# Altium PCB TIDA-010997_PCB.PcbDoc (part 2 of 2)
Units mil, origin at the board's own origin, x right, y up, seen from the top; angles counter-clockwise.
Board outline 2300 x 1800 mil, 2 copper layers (Top Layer, Bottom Layer), stack 62 mil thick; 121 components, 80 nets, 346 pads, 277 vias.
Unrouted connection lines stored in the file: 141.
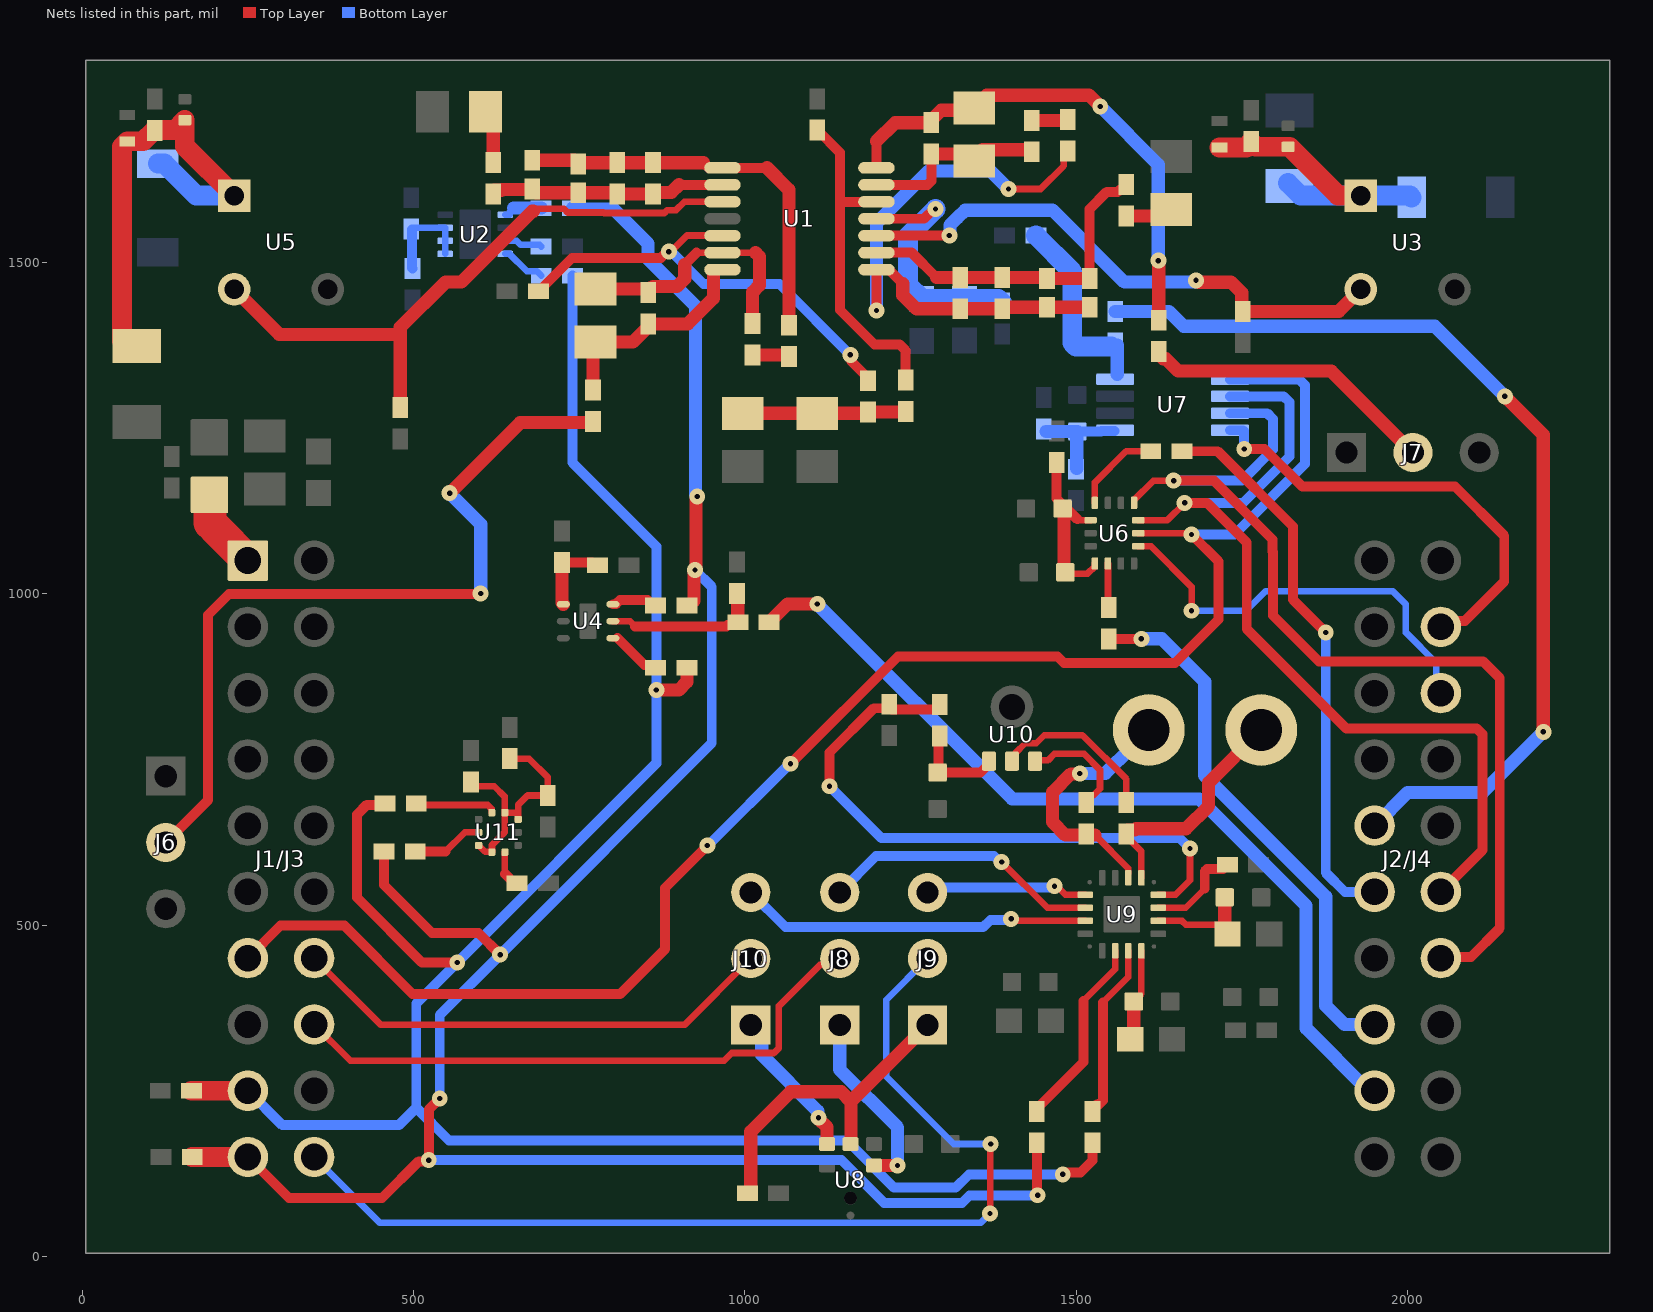
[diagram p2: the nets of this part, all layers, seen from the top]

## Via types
v1: diameter 24, hole 8, Top Layer to Bottom Layer, tented both sides, 271 vias
v2: diameter 19.68, hole 7.87, Top Layer to Bottom Layer, tented both sides, 6 vias

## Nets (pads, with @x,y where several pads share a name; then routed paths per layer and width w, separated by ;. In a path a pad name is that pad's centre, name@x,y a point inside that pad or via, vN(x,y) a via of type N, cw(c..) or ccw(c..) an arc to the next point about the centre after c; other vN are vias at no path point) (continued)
I2C_SCL: J1/J3.9 R6.1 R17.1 R21.2 R39.2 R44.1 | length 3379.6
  Top Layer w15: R44.1@456.84,683.31 454.94,681.41 429.35,681.41 414.46,666.52 414.46,541.58 512.41,443.63 v1(565.9,443.63) ; v1(1479.54,123.81) 1482.21,126.49 1506.15,126.49 1524.32,144.66 R39.2@1524.32,171.5
  Top Layer w20: v1(866.29,854.65) 900.16,854.65 912.5,866.99 R21.2@912.5,887.99
  Top Layer w30: R17.1@165.08,250 J1/J3.9@249.96,250
  Bottom Layer w15: J1/J3.9@249.96,250 301.96,198 477.77,198 504.08,224.31 ; v1(565.9,443.63) 504.08,381.81 504.08,224.31 ; v1@567.62,445.35 866.29,744.02 v1(866.29,854.65) 866.29,1071.22 739.84,1197.67 R6.1@739.84,1479.94 ; v1(1479.54,123.81) 1337.94,123.81 1317.85,103.72 1225.12,103.72 1153.97,174.87 553.52,174.87 504.08,224.31
I2C_SDA: J1/J3.10 R8.1 R18.1 R22.2 R38.2 R45.1 | length 3505.2
  Top Layer w10: R22.2@912.5,982.24 916.43,982.24 R22.2@923.24,989.05 ; v1@923.24,1035.69 v1@926.32,1038.77 ; v1@926.32,1144.8 v1(928.02,1146.5) ; R38.2@1440.09,171.5 R38.2@1440.88,170.72 ; v1@1440.88,93.12 v1(1441.66,92.34)
  Top Layer w15: J1/J3.10@249.96,150 312,87.96 452.27,87.96 507.85,143.54 521.24,143.54 v1(522.96,145.26) 522.96,221.63 v1(539.52,238.19) ; R45.1@455.34,611.07 455.34,560.6 527.9,488.03 597.94,488.03 v1(630.69,455.28) ; v1@1440.88,93.12 R38.2@1440.88,170.72
  Top Layer w20: R22.2@923.24,989.05 v1@923.24,1035.69 ; v1@926.32,1038.77 v1@926.32,1144.8
  Top Layer w30: R18.1@166.08,150 J1/J3.10@249.96,150
  Bottom Layer w15: v1(522.96,145.26) 1145.72,145.26 1210.13,80.85 1327.33,80.85 1338.62,92.14 1441.47,92.14 v1(1441.66,92.34) ; v1(539.52,238.19) 539.52,364.12 v1(630.69,455.28) 949.93,774.52 949.93,1010.38 v1(924.62,1035.69)
  Bottom Layer w20: R8.1@739.78,1581.82 741.5,1580.11 802,1580.11 853.59,1528.52 853.59,1505.42 925.43,1433.57 925.43,1149.09 v1(928.02,1146.5)
I2S_SCLK: J1/J3.28 J8.2 | length 916.8
  Top Layer w10: J1/J3.28@349.96,350 404.68,295.28 968.46,295.28 980.12,306.93 1043.7,306.93 1051.25,314.47 1051.25,378.06 1113.13,439.94 1133.6,439.94 J8.2@1142.99,449.33
I2S_SCLK_DMIC: J8.1 U8.4 | length 283.9
  Top Layer w20: U8.4@1194.69,137.25 v1(1230.32,137.25)
  Bottom Layer w20: J8.1@1142.99,349.33 1142.99,282.01 1230.32,194.68 v1(1230.32,137.25)
I2S_SCLK_TAA: J8.3 U9.7 | length 425.6
  Top Layer w10: v1(1387.26,595.05) 1456.29,526.02 U9.7@1513.5,526.02
  Bottom Layer w15: J8.3@1142.99,549.33 1197.79,604.13 1375.74,604.13 1384.82,595.05 v1(1387.26,595.05)
I2S_SD: J1/J3.30 J9.2 | length 1575.4
  Top Layer w10: v1(1369.75,64.76) 1370.27,65.29 1370.27,169.09 v1(1370.8,169.61)
  Bottom Layer w10: J1/J3.30@349.96,150 449.31,50.65 1355.63,50.65 v1(1369.75,64.76) ; J9.2@1275.52,449.33 1213.24,387.05 1213.24,271.54 1315.17,169.61 v1(1370.8,169.61)
I2S_SD_DMIC: J9.1 R36.2 U8.6 | length 504.9
  Top Layer w20: R36.2@1003.61,95.41 1008.84,100.64 1008.84,188.47 1068.85,248.48 1145.25,248.48 1159.96,233.77 ; U8.6@1159.96,169.61 1159.96,233.77 ; J9.1@1275.52,349.33 1159.96,233.77
I2S_SD_TAA: J9.3 U9.6 | length 247.9
  Top Layer w10: v1(1466.95,558.65) 1470.74,558.65 1483.68,545.71 U9.6@1513.5,545.71
  Bottom Layer w15: J9.3@1275.52,549.33 1283.95,557.76 1284.79,556.93 1465.23,556.93 v1(1466.95,558.65)
I2S_WS: J1/J3.27 J10.2 | length 742
  Top Layer w10: J1/J3.27@349.96,450 450.63,349.33 908.84,349.33 J10.2@1008.84,449.33
I2S_WS_DMIC: J10.1 U8.1 | length 227.3
  Top Layer w20: v1(1110.85,209.26) 1110.85,207.87 1123.83,194.89 U8.1@1123.83,169.61
  Bottom Layer w20: J10.1@1008.84,349.33 1025.23,332.94 1025.23,304.23 1110.08,219.38 1110.08,210.02 v1(1110.85,209.26)
I2S_WS_TAA: J10.3 U9.8 | length 532.8
  Top Layer w10: v1(1401.6,509.33) 1404.27,506.65 1414.14,506.65 1414.45,506.34 U9.8@1513.5,506.34
  Bottom Layer w15: J10.3@1008.84,549.33 1061.34,496.84 1359.6,496.84 1370.37,507.61 1399.87,507.61 v1(1401.6,509.33)
INERT_INTR1: J2/J4.35 R32.1 | length 842.9
  Top Layer w15: R32.1@1659.57,1214.91 1713.38,1214.91 1826.85,1101.44 1826.85,990.9 v1(1876.32,941.43)
  Bottom Layer w15: v1(1876.32,941.43) 1876.32,578.92 1905.24,550 J2/J4.35@1950,550
INERT_INTR2: J2/J4.33 R33.1 | length 821.2
  Top Layer w15: R33.1@1549.14,931.89 v1(1598.14,931.89)
  Bottom Layer w20: v1(1598.14,931.89) 1628.9,931.89 1693.81,866.99 1693.81,725.55 1876.32,543.04 1876.32,378.27 1904.49,350.11 1949.89,350.11 J2/J4.33@1950,350
Magnet_INTR: J2/J4.36 R35.1 | length 1484.7
  Top Layer w20: v1(2146.57,1297.82) 2204.72,1239.66 v1(2204.72,791.55)
  Bottom Layer w20: R35.1@1558.57,1425.82 1639.78,1425.82 1662.08,1403.52 2040.86,1403.52 v1(2146.57,1297.82) ; J2/J4.36@1950,650 2000.04,700.04 2113.21,700.04 v1(2204.72,791.55)
NetC4_1: C4.1 C5.1 R3.2 U1.4 | length 380.9
  Top Layer w15: U1.4@1198.38,1565.73 1270.21,1565.73 1285.07,1580.58 v1(1287.51,1580.58)
  Bottom Layer w30: v1(1287.51,1580.58) 1246.18,1539.25 1246.18,1465.98 1266.73,1445.42 C4.1@1266.73,1444.44 1330.77,1444.44 C5.1@1331.11,1444.78 1382.13,1444.78 R3.2@1387.99,1438.92
NetC6_1: C6.1 R2.1 U2.5 U2.6 U2.7 | length 149.9
  Bottom Layer w10: C6.1@497.46,1549.24 500.23,1552.01 U2.7@547.68,1552.01 U2.6@547.68,1532.32 U2.5@547.68,1512.64
  Bottom Layer w15: C6.1@497.46,1549.24 497.46,1491.51 R2.1@498.46,1490.51
NetC7_1: C7.1 C13.2 D1.2 D2.1 R11.2 U1.1 | length 917
  Top Layer w10: v1(1397.55,1610.69) 1446.15,1610.69 1481.02,1645.56 1481.02,1661.84 C13.2@1487.27,1668.08
  Top Layer w15: v1(1198.38,1427.33) U1.1@1198.38,1488.95 1217.08,1488.95 1238.26,1467.78
  Top Layer w20: 1238.26,1467.78 1238.26,1450.33 1258.7,1429.89 C7.1@1325,1429.89 1325.08,1429.97 R11.2@1387.99,1429.97 1390.24,1432.22 D1.2@1455.85,1432.22 D2.1@1520.16,1432.22
  Bottom Layer w20: v1(1198.38,1427.33) 1198.38,1559.22 1277.07,1637.91 1370.33,1637.91 v1(1397.55,1610.69)
NetC7_2: C7.2 D1.1 D2.2 R7.2 R11.1 U1.2 | length 515.8
  Top Layer w15: U1.2@1198.38,1514.55 1251.7,1514.55 1289.11,1477.13 ; D1.1@1454.17,1477.21 D1.1@1455.85,1475.53 ; D2.2@1520.16,1475.53 1520.16,1580.58 1545.97,1606.4 1562.43,1606.4 1564.93,1608.9 1571.22,1608.9 1575.53,1613.21 R7.2@1575.53,1617.15
  Top Layer w20: 1289.11,1477.13 C7.2@1325,1477.13 R11.1@1387.91,1477.13 ; R11.1@1387.99,1477.21 D1.1@1454.17,1477.21 ; D1.1@1455.85,1475.53 D2.2@1520.16,1475.53
NetC8_2: C8.2 C10.1 C11.1 C44.1 R5.1 U3.1 | length 447.8
  Top Layer w30: C11.1@1715.91,1673.35 1757,1673.35 1763.81,1680.16 C10.1@1763.81,1682.15 1763.81,1681.09 1770.63,1674.28 C8.2@1819.54,1674.28 1821.51,1674.28 1895.08,1600.71 U3.1@1929.29,1600.71
  Bottom Layer w30: R5.1@1819.54,1619.48 1838.31,1600.71 U3.1@1929.29,1600.71 2003.22,1600.71 C44.1@2005.91,1598.03
NetC9_1: C9.1 R9.2 R13.1 U1.7 | length 775
  Top Layer w10: R9.2@1345.87,1732.85 R9.2@1365.04,1752.01 ; v1(1623.73,1502.54) v1@1624.34,1501.94
  Top Layer w15: U1.7@1198.38,1642.5 1198.38,1682.5
  Top Layer w20: 1198.38,1682.5 1226.62,1710.75 C9.1@1281.19,1710.75 1281.19,1714.68 1296.09,1729.58 1342.61,1729.58 R9.2@1345.87,1732.85 ; R9.2@1365.04,1752.01 1519.28,1752.01 v1(1536.08,1735.21) ; R13.1@1624.34,1412.49 v1@1624.34,1501.94
  Bottom Layer w20: v1(1536.08,1735.21) 1623.73,1647.56 v1(1623.73,1502.54)
NetC9_2: C9.2 R9.1 R12.2 U1.6 | length 281.1
  Top Layer w10: R9.1@1352.2,1663.5 R9.1@1358.41,1669.71 ; R12.2@1429.66,1669.71 R12.2@1432.53,1666.84
  Top Layer w15: U1.6@1198.38,1616.91 1275.33,1616.91 1281.19,1622.77 C9.2@1281.19,1663.5
  Top Layer w20: C9.2@1281.19,1663.5 R9.1@1352.2,1663.5 ; R9.1@1358.41,1669.71 R12.2@1429.66,1669.71
NetC12_1: C12.1 R7.1 | length 71.7
  Top Layer w10: C12.1@1633.53,1569.9 C12.1@1643.21,1579.59
  Top Layer w20: R7.1@1575.53,1569.9 C12.1@1633.53,1569.9
NetC13_1: C13.1 R12.1 | length 55.3
  Top Layer w10: C13.1@1486.02,1714.08 C13.1@1487.27,1715.33
  Top Layer w20: R12.1@1432.53,1714.08 C13.1@1486.02,1714.08
NetC14_1: C14.1 R16.1 U1.5 | length 509.6
  Top Layer w15: C14.1@1109.29,1699.43 1143.35,1665.37 1143.35,1591.32 ; U1.5@1198.38,1591.32 1143.35,1591.32 ; R16.1@1242.38,1322.33 1242.38,1367.34 1233.6,1376.13 1195.38,1376.13 1143.35,1428.15 1143.35,1591.32
NetC15_1: C15.1 R20.1 U4.1 | length 119.5
  Top Layer w15: R20.1@723.87,1047.12 769.37,1047.12 773.75,1042.74 C15.1@777.68,1042.74
  Top Layer w20: R20.1@723.87,1047.12 723.87,986.07 U4.1@725.85,984.08
NetC16_1: C16.1 C22.2 D3.2 D4.1 R27.2 U1.8 | length 612
  Top Layer w15: 937.48,1650.32 945.31,1642.5 U1.8@966.1,1642.5 1033.27,1642.5
  Top Layer w20: D3.2@678.92,1654 742.69,1654 D4.1@748.33,1648.35 750.3,1650.32 R27.2@807.58,1650.32 937.48,1650.32 ; 1033.27,1642.5 1066.37,1609.41 C22.2@1066.37,1404.97
NetC16_2: C16.2 D3.1 D4.2 R25.2 R27.1 U1.9 | length 360.3
  Top Layer w15: 900.5,1616.91 U1.9@966.1,1616.91
  Top Layer w20: R25.2@620.08,1603.08 620.08,1607.02 621.89,1608.83 632.54,1608.83 633.61,1609.89 D3.1@678.92,1609.89 ; D3.1@678.92,1610.69 684.56,1605.05 D4.2@748.33,1605.05 805.61,1605.05 R27.1@807.58,1603.08 C16.2@861.34,1603.08 861.34,1603.6 863.15,1605.41 889,1605.41 900.5,1616.91
NetC17_2: C17.2 C19.1 C20.1 C45.1 R24.1 U5.1 | length 695.7
  Top Layer w30: R24.1@67.95,1373.29 60,1381.24 60,1674.44 68.14,1682.59 91.89,1682.59 108.26,1698.97 C19.1@109.46,1698.97 110.21,1699.72 140.01,1699.72 C17.2@154.8,1714.51 154.8,1699.72 154.8,1675.2 U5.1@229.29,1600.71
  Bottom Layer w30: C45.1@114.09,1648.92 123.93,1648.92 172.14,1600.71 U5.1@229.29,1600.71
NetC18_1: C18.1 R26.2 R29.1 U1.14 | length 336.3
  Top Layer w15: U1.14@952.39,1485.39 955.96,1488.95 U1.14@966.1,1488.95
  Top Layer w20: R29.1@770.83,1307.3 770.83,1376.13 R26.2@774.33,1379.63 830.86,1379.63 854.3,1403.07 C18.1@854.3,1407.01 913.62,1407.01 952.39,1445.78 U1.14@952.39,1485.39
NetC18_2: C18.2 R26.1 R28.2 U1.13 | length 394.2
  Top Layer w10: 926.94,1514.55 1016.03,1514.55
  Top Layer w15: 909.25,1496.85 926.94,1514.55
  Top Layer w20: R26.1@774.33,1459.63 848.92,1459.63 C18.2@854.3,1454.25 ; C18.2@854.3,1456.81 861.11,1463.62 897.52,1463.62 909.25,1475.35 909.25,1496.85 ; R28.2@1011.48,1407.48 1011.48,1454.92 1021.89,1465.33 1021.89,1508.69 1016.03,1514.55
NetC21_1: C21.1 R25.1 | length 81.6
  Top Layer w10: C21.1@608.46,1727.12 C21.1@620.08,1715.51
  Top Layer w20: R25.1@620.08,1650.32 C21.1@620.08,1715.51
NetC22_1: C22.1 R28.1 | length 55.9
  Top Layer w10: C22.1@1063.86,1360.23 C22.1@1066.37,1357.73
  Top Layer w20: R28.1@1011.48,1360.23 C22.1@1063.86,1360.23
NetC23_1: C23.1 R31.1 U1.12 | length 699.2
  Top Layer w10: v1@888.18,1516.14 912.5,1540.45 U1.12@965.78,1540.45 ; R31.1@1185.62,1321.33 R31.1@1185.62,1325.27
  Top Layer w15: C23.1@689.29,1456.96 693.23,1456.96 696.71,1460.44 696.71,1464.38 738.85,1506.51 873.06,1506.51 882.68,1516.14 v1(885.12,1516.14) ; U1.12@965.78,1540.45 U1.12@966.1,1540.14 ; v1(1159.02,1360.37) 1160.74,1358.64 1160.74,1350.15 R31.1@1185.62,1325.27
  Bottom Layer w15: v1(885.12,1516.14) 888.73,1516.14 937.56,1467.3 1052.08,1467.3 v1(1159.02,1360.37)
NetC24_2: C24.2 C25.2 R40.1 U6.5 U6.8 | length 271.8
  Top Layer w10: C24.2@1479.34,1128.35 C24.2@1481.38,1126.32 ; C25.2@1481.38,1034.29 1485.42,1030.24 1517.02,1030.24 1528,1041.22 U6.8@1528,1045.49 ; 1501.53,1112.3 1502.89,1110.94 U6.5@1521.6,1110.94
  Top Layer w15: 1470.03,1143.29 1470.29,1143.55 ; R40.1@1470.29,1198.12 1470.29,1143.55 ; 1501.53,1112.3 1470.29,1143.55
  Top Layer w20: C25.2@1481.38,1034.29 C24.2@1481.38,1126.32
NetC26_2: C26.2 C27.1 R34.1 U7.5 | length 168.2
  Bottom Layer w10: C27.1@1450.66,1248.6 C27.1@1454.6,1244.67
  Bottom Layer w15: R34.1@1499.43,1187.7 R34.1@1500.52,1188.78 ; C26.2@1500.52,1243.58 C26.2@1502.58,1245.65 ; C26.2@1501.6,1244.67 1536.92,1244.67 1537.9,1245.65 U7.5@1557.59,1245.65
  Bottom Layer w20: C27.1@1454.6,1244.67 C26.2@1501.6,1244.67 ; R34.1@1500.52,1188.78 C26.2@1500.52,1243.58
NetC33_1: C33.1 C37.2 U9.17 | length 169.3
  Top Layer w10: U9.17@1623.73,506.34 1659.57,506.34 1665.55,500.35 1714.35,500.35 C37.2@1728.06,486.65 C37.2@1723.93,490.78
  Top Layer w20: C37.2@1723.93,490.78 C33.1@1723.93,541.77
NetC34_1: C34.1 C38.2 U9.14 | length 140.2
  Top Layer w10: C38.2@1581.41,327.78 C38.2@1586.56,332.94 ; C34.1@1586.56,384.57 1598.14,396.15 U9.14@1598.14,461.06
  Top Layer w20: C38.2@1586.56,332.94 C34.1@1586.56,384.57
NetC35_1: C35.1 R37.2 U9.19 | length 945.7
  Top Layer w10: U9.19@1623.73,545.71 1649.57,545.71 1671.47,567.61 v1(1671.47,615.44)
  Top Layer w15: v1(1127.58,709.43) 1127.58,760.28 1194.42,827.12 1213.44,827.12 1217.76,831.43 C35.1@1217.76,833.17 1217.76,829.82 1222.07,825.51 1289.58,825.51 1293.89,829.82 R37.2@1293.89,832.78
  Bottom Layer w15: v1(1127.58,709.43) 1205.65,631.37 1655.55,631.37 v1(1671.47,615.44)
NetC36_1: C36.1 U9.18 | length 146.5
  Top Layer w10: U9.18@1623.73,526.02 1665.02,526.02 1693.81,554.81 ; C36.1@1721.33,584.45 C36.1@1727.86,590.98
  Top Layer w15: 1693.81,554.81 1693.81,581.14 1697.12,584.45 C36.1@1721.33,584.45
NetC39_2: C39.2 R37.1 U10.1 | length 143.5
  Top Layer w15: R37.1@1293.89,785.54 1292.32,783.96 1292.32,731.81 C39.2@1290.74,730.23 1355.27,730.23 1368.28,743.25 U10.1@1368.28,747.18
NetC40_1: C40.1 U10.2 | length 255.9
  Top Layer w10: U10.2@1402.93,747.18 1408.36,752.62 1408.36,759.82 1422.97,774.43 1439.54,774.43 1451.58,786.46 1509.21,786.46 1575.53,720.14 C40.1@1575.53,684.79
NetC40_2: C40.2 TP1.1 U9.1 | length 363.2
  Top Layer w10: C40.2@1575.53,633.61 1598.14,610.99 U9.1@1598.14,571.3
  Top Layer w20: C40.2@1575.53,637.55 1575.53,641.48 1577.34,643.29 1588.42,643.29 1590.45,645.32 1665.34,645.32 1699.57,679.54 1699.57,714.9 TP1.1@1779.04,794.38
NetC41_1: C41.1 U10.3 | length 173.1
  Top Layer w10: U10.3@1437.57,747.18 1438.9,748.51 1457.15,748.51 1467.01,758.37 1511.54,758.37 1535.7,734.21 1535.7,705.72 1525.6,695.61 1521.66,695.61 1514.85,688.8 C41.1@1514.85,684.86
NetC41_2: C41.2 TP2.1 U9.2 | length 396.2
  Top Layer w10: 1528.12,635.74 1578.38,585.48 U9.2@1578.38,578.11
  Top Layer w20: v1(1505.3,728.78) 1504.54,728.01 1491.83,728.01 1464.08,700.26 1464.08,655.32 1483.62,635.78 1513.04,635.78 C41.2@1514.85,637.62 ; C41.2@1514.85,635.74 1528.12,635.74
  Bottom Layer w20: v1(1505.3,728.78) 1543.78,728.78 1582.79,767.79 1582.79,794.38 TP2.1@1609.38,794.38
NetC42_1: C42.1 C43.1 R42.1 U11.1 U11.5 U11.6 U11.10 | length 366.1
  Top Layer w10: C42.1@586.54,715.95 593.05,709.43 621.86,709.43 637.41,693.89 637.41,639.84 618.35,620.78 618.35,610.33 U11.6@618.04,610.02 618.04,610.31 617.72,610.63 607.88,610.63 598.35,620.15 U11.5@598.06,620.15 ; U11.1@637.72,669.66 657.06,669.66 657.8,670.4 ; R42.1@645.05,751.03 674.32,751.03 702.68,722.67 C43.1@702.68,695.48 672.1,695.48 657.8,681.18 657.8,670.4 ; U11.10@657.39,659.84 U11.10@657.7,659.52 657.8,659.62 657.8,670.4
NetJ1/J3_1: J1/J3.1 R1.2 | length 123.1
  Top Layer w20: R1.2@192,1149.07 R1.2@201.16,1139.91
  Top Layer w50: 192.99,1106.97 R1.2@192.99,1148.08 ; 201.16,1098.8 J1/J3.1@249.96,1050
NetR4_1: R4.1 U2.3 | length 57.8
  Bottom Layer w10: U2.3@638.24,1532.32 655.75,1532.32 661.79,1526.29 690.1,1526.29 R4.1@692.54,1523.85
NetR6_2: R6.2 U2.4 | length 67.9
  Bottom Layer w10: U2.4@638.24,1512.64 644.97,1512.64 670.86,1486.75 685.78,1486.75 R6.2@692.59,1479.94
NetR8_2: R8.2 U2.1 | length 60.9
  Bottom Layer w10: U2.1@638.24,1571.69 644.97,1571.69 645.05,1571.77 645.05,1575.89 650.98,1581.82
  Bottom Layer w20: 650.98,1581.82 R8.2@692.54,1581.82
NetR10_1: R10.1 R15.1 R16.2 R31.2 | length 247
  Top Layer w20: R10.1@996.64,1272.08 R15.1@1109.29,1272.08 1183.61,1272.08 R31.2@1185.62,1274.09 1241.38,1274.09 R16.2@1242.38,1275.09
NetR14_2: R14.2 U1.3 U3.2 | length 848.6
  Top Layer w15: U1.3@1198.38,1540.14 1308.14,1540.14 v1(1308.46,1540.45)
  Top Layer w20: v1(1680.69,1472.76) 1681.78,1472.76 1684.46,1470.08 1733.5,1470.08 1749.46,1454.13 1749.46,1427.76 R14.2@1751.27,1425.95 1895.95,1425.95 U3.2@1929.29,1459.29
  Bottom Layer w20: v1(1308.46,1540.45) 1309.22,1541.21 1309.22,1555.81 1320.38,1566.97 ; 1320.38,1566.99 1332.1,1578.7 1464.08,1578.7 1572.66,1470.12 v1@1680.24,1470.12
NetR19_1: R19.1 R23.1 U4.5 | length 225.6
  Top Layer w10: U4.5@800.66,958.49 826.61,958.49 834.31,950.79
  Top Layer w15: 834.31,950.79 972.24,950.79 973.89,952.44 984.97,952.44 R23.1@989.28,956.75
  Top Layer w20: R23.1@989.28,956.75 R19.1@989.28,988.04
NetR21_1: R21.1 U4.4 | length 83.2
  Top Layer w10: U4.4@800.66,932.9 U4.4@807.87,932.9
  Top Layer w15: U4.4@807.87,932.9 848.47,892.3 860.94,892.3 R21.1@865.25,887.99
NetR22_1: R22.1 U4.6 | length 71.2
  Top Layer w15: U4.6@800.66,984.08 805.42,984.08 805.5,984.16 805.5,984.75 811.44,990.69 852.87,990.69 861.32,982.24 R22.1@865.25,982.24
NetR30_2: R30.2 U1.10 U5.2 | length 968.5
  Top Layer w10: 680.62,1577.07 684.54,1580.99 726.62,1580.99 732.5,1575.11 786.63,1575.11 787.28,1574.46 878.48,1574.46 882.73,1578.7 896.11,1578.7 908.72,1591.32 U1.10@966.1,1591.32
  Top Layer w20: U5.2@229.29,1459.29 297.45,1391.13 477.38,1391.13 479.96,1393.7 479.96,1401.89 548.18,1470.12 572.04,1470.12 678.99,1577.07 680.62,1577.07 ; R30.2@479.96,1280.75 479.96,1391.13
NetR32_2: R32.2 U6.4 | length 134.6
  Top Layer w10: U6.4@1528,1137.03 1528,1167.71 1575.2,1214.91 R32.2@1612.32,1214.91
NetR33_2: R33.2 U6.9 | length 67
  Top Layer w10: U6.9@1547.69,1045.49 1547.77,1045.41 1547.77,980.51 R33.2@1549.14,979.13
NetR35_2: R35.2 R41.1 U7.8 | length 298.2
  Bottom Layer w10: R35.2@1552.71,1372.72 1553.69,1372.72 R35.2@1558.57,1367.83
  Bottom Layer w20: U7.8@1561.61,1330.91 R35.2@1561.61,1375.33
  Bottom Layer w30: R41.1@1438.98,1540.45 1493.81,1485.61 1493.81,1378.57 1499.67,1372.72 R35.2@1552.71,1372.72
NetR38_1: R38.1 U9.12 | length 291.5
  Top Layer w10: R38.1@1440.09,218.75 R38.1@1440.09,222.68 ; 1510.72,385.73 1558.77,433.78 U9.12@1558.77,461.06
  Top Layer w15: R38.1@1440.09,222.68 1510.72,293.32 1510.72,385.73
NetR39_1: R39.1 U9.13 | length 266.6
  Top Layer w10: R39.1@1524.32,218.75 R39.1@1524.32,222.68 ; 1540.19,383.41 1578.46,421.69 U9.13@1578.46,461.06
  Top Layer w15: R39.1@1524.32,222.68 1531.14,229.5 1534.33,229.5 1540.19,235.35 1540.19,383.41
NetR43_1: R43.1 U11.7 | length 57
  Top Layer w10: 637.72,577.35 U11.7@637.72,610.02 ; R43.1@652.13,562.94 R43.1@656.07,562.94
  Top Layer w15: 637.72,577.35 R43.1@652.13,562.94
NetR44_2: R44.2 U11.2 | length 128.6
  Top Layer w10: R44.2@497.31,681.18 611.86,681.18 617.72,675.32 617.72,669.98 U11.2@618.04,669.66
NetR45_2: R45.2 U11.4 | length 107.4
  Top Layer w10: 548.35,611.07 577.12,639.84 U11.4@598.06,639.84
  Top Layer w15: R45.2@502.58,611.07 548.35,611.07
OPT_INTR: J2/J4.32 R23.2 | length 1337.5
  Top Layer w20: R23.2@1036.52,956.75 1064.09,984.32 v1(1109.29,984.32)
  Bottom Layer w20: v1(1109.29,984.32) 1403.25,690.35 1685.58,690.35 1846.73,529.2 1846.73,344.11 1940.84,250 J2/J4.32@1950,250
PIR1_IN: J7.2 R13.2 | length 448.9
  Top Layer w20: R13.2@1624.34,1365.25 1624.34,1361.31 1631.15,1354.5 1635.08,1354.5 1653.73,1335.85 1884.98,1335.85 J7.2@2007.87,1212.96
PIR2_IN: J6.2 R29.2 | length 1226.5
  Top Layer w15: J6.2@126.04,624.66 189.68,688.3 189.68,967.79 221.51,999.61 600.48,999.61 v1(601.25,1000.38)
  Top Layer w20: v1(554.46,1151.66) 661.04,1258.25 769.02,1258.25 R29.2@770.83,1260.06
  Bottom Layer w20: v1(554.46,1151.66) 601.25,1104.88 v1(601.25,1000.38)
SPI_CLK: J1/J3.7 U6.13 U7.1 | length 2501
  Top Layer w10: U6.13@1593.45,1091.26 1593.53,1091.18 v1@1672.04,1091.18
  Top Layer w15: J1/J3.7@249.96,450 299.12,499.16 395.5,499.16 498.51,396.15 811.83,396.15 879.21,463.54 879.21,556.06 v1(943.31,620.15) ; v1(1068.85,743.38) 1230.72,905.25 1471.77,905.25 1481.5,895.51 1648.78,895.51 1714.35,961.08 1714.35,1048.87 v1(1673.93,1089.29) v1@1672.04,1091.18
  Bottom Layer w10: v1(943.31,620.15) v1@944.46,620.15 ; v1@1067.69,743.38 v1(1068.85,743.38)
  Bottom Layer w15: v1@944.46,620.15 v1@1067.69,743.38 ; v1(1673.93,1089.29) 1738.49,1089.29 1845.18,1195.98 1845.18,1314.62 1836.39,1323.41 U7.1@1731.8,1323.41
SPI_CS_1: J2/J4.18 U6.12 | length 641.4
  Top Layer w10: U6.12@1593.45,1071.57 1612.63,1071.57 1673.93,1010.27 v1(1673.93,974.24)
  Bottom Layer w10: v1(1673.93,974.24) 1756.23,974.24 1785.88,1003.9 1977.04,1003.9 1997.22,983.72 1997.22,941.43 2043.13,895.51 2043.13,856.87 J2/J4.18@2050,850
SPI_CS_2: J2/J4.19 U7.4 | length 688.2
  Top Layer w15: v1(1753.45,1218.43) 1784.01,1218.43 1840.91,1161.53 2071.47,1161.53 2145.67,1087.33 2145.67,1018.2 2086.22,958.75 2058.75,958.75 J2/J4.19@2050,950
  Bottom Layer w15: U7.4@1731.8,1246.63 1751.36,1246.63 1752.72,1245.28 1752.72,1219.16 v1(1753.45,1218.43)
SPI_MISO: J2/J4.14 U6.1 U7.3 | length 1523.6
  Top Layer w10: U6.1@1587.14,1141.38 1616.26,1170.5 v1(1646.89,1170.5)
  Top Layer w15: v1(1646.89,1170.5) 1707.64,1170.5 1796.25,1081.89 1796.25,1063.53 1796.92,1062.86 1796.92,967 1866.08,897.84 2113.97,897.84 2138.89,872.92 2138.89,495.19 2095.51,451.81 2051.81,451.81 J2/J4.14@2050,450
  Bottom Layer w15: v1(1646.89,1170.5) 1750.09,1170.5 1796.92,1217.33 1796.92,1263.44 1788.13,1272.22 U7.3@1731.8,1272.22
SPI_MOSI: J2/J4.15 U6.14 U7.2 | length 1377.8
  Top Layer w10: U6.14@1593.45,1110.94 1637.42,1110.94 v1(1663.51,1137.03)
  Top Layer w15: v1(1663.51,1137.03) 1697.47,1137.03 1757.12,1077.39 1757.12,946.92 1907.27,796.77 2104.21,796.77 2113,787.98 2113,613 J2/J4.15@2050,550
  Bottom Layer w15: v1(1663.51,1137.03) 1751.5,1137.03 1821.51,1207.04 1821.51,1289.03 1812.73,1297.82 U7.2@1731.8,1297.82
pads on no net: J1/J3.3 J1/J3.4 J1/J3.5 J1/J3.8 J1/J3.21 J1/J3.25 J1/J3.26 J1/J3.29 J2/J4.11 J2/J4.12 J2/J4.13 J2/J4.16 J2/J4.17 J2/J4.34 J2/J4.37 J2/J4.38 U2.9 U6.2 U6.3 U6.10 U6.11 U8. U9.3 U9.4 U10.

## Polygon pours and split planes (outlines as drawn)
NetC6_1 on Bottom Layer "BOTTOM_LAYER_NETC6_1_P000" (solid, remove dead copper, pour order 0): 557.07,1511.42 521.77,1476.12 501.75,1476.12 500.41,1474.79 485.39,1474.52 484.34,1475.58 484.34,1557.28 559.18,1557.28 559.18,1511.42
3V3_EVM on Bottom Layer "BOTTOM_LAYER_3V3_EVM_P001" (solid, remove dead copper, pour order 1): 32.51,1316.21 40.76,1324.46 158.34,1324.46 188.54,1354.65 188.89,1354.3 366.69,1354.3 387.2,1333.79 387.2,1194.78 328.24,1194.78 309.78,1213.23 238.8,1213.23 235.5,1216.53 228.22,1209.24 164.46,1209.24 146.37,1191.15 123.35,1191.15 122.3,1192.19 47,1192.19 30.27,1208.93 32.51,1211.18
GND on Bottom Layer "BOTTOM_LAYER_GND_P004" (solid, remove dead copper, pour order 4): 2312.99,1811.02 2312.99,0 0,0 0,1811.02
GND on Top Layer "TOP_LAYER_GND_P002" (solid, remove dead copper, pour order 2): 1612.32,609.81 1645.97,609.81 1654.71,601.07 1654.71,575.97 1639.42,560.68 1618.37,560.68 1612.32,566.73
NetC42_1 on Top Layer "TOP_LAYER_NETC42_1_P003" (solid, remove dead copper, pour order 3): 636.08,762.92 639.72,766.56 667.53,766.56 714.89,719.2 714.89,679.94 691.53,679.94 691.21,679.63 672.21,679.63 672.21,662.18 664.42,654.39 655.07,654.39 652.89,656.57 632.95,656.57 632.95,690.85 619.55,704.25 598.36,704.25 595.56,701.44 579.36,701.44 579.36,731.35 578.42,732.29 618.3,732.29 634.2,748.18 634.2,765.94
GND on Top Layer "TOP_LAYER_GND_P006" (solid, remove dead copper, pour order 6): -0.04,1811.06 0,1811.02 0,0.04 2312.99,0.04 2312.99,1811.06
3V3_EVM on Top Layer "TOP_LAYER_3V3_EVM_P005" (solid, remove dead copper, pour order 5): 32.51,1317.82 40.76,1326.07 158.34,1326.07 188.54,1356.26 188.89,1355.91 366.69,1355.91 387.2,1335.4 387.2,1196.39 328.24,1196.39 309.78,1214.84 238.8,1214.84 235.5,1218.14 228.22,1210.85 164.46,1210.85 146.37,1192.76 123.35,1192.76 122.3,1193.8 47,1193.8 30.27,1210.54 32.51,1212.79

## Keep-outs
Keep-Out Layer:
  text ".Layer_Name" at 577,-858.49 h60

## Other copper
Top Layer:
  text ".Layer_Name" at 577,-858.49 h60
Bottom Layer:
  text ".Layer_Name" at 577,-858.49 h60

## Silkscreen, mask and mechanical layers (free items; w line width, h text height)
Top Overlay:
  circle w10: c1255.09,984 r21.73
  lines w3.94: 638.75,817.76 815.65,817.76 815.65,648.23 1148.45,648.23 1148.45,817.76 ; 1798.34,900.03 1876.04,900.03 1895.95,900.03 1895.95,1095.25 1798.34,1095.25 1798.34,1301.27
  lines w4: 638.75,817.76 638.75,1128.86 1148.45,1128.86 1148.45,817.76 ; 1798.34,900.03 1196.52,900.03 1196.52,1301.27 1798.34,1301.27 ; 404.81,339.52 794.64,339.52 794.64,801.08 404.81,801.08 404.81,339.52 ; 922.15,29.53 1331.11,29.53 1331.11,277.94 922.15,277.94 922.15,29.53 ; 1173.05,645.43 1173.05,892.2 1877.93,892.2 1877.93,91.38 1350.65,91.38 1350.65,645.43 1173.05,645.43
  lines w10: 1231.27,1187.24 1256.22,1212.18 1270.35,1198.05 1270.35,1197.79 1283.06,1185.08 ; 1256.12,1008.4 1256.12,1212.18 ; 1279.6,985.75 1402.92,985.75 1370.61,1018.05 ; 1378.93,961.61 1402.56,985.24
  lines w15: 509.43,1172.28 544.31,1137.41 ; 579.49,1176.7 579.49,1174.08 543.96,1138.54 543.96,1378.82 709.02,1378.82 693.09,1394.75 ; 693.02,1363.72 707.38,1378.08
  lines w20: 1255.09,984 1255.09,984.66
  text "PIR1" at 2214.48,1588.12 h50 r270
  text "PIR2" at 528.96,1576.32 h50 r270
  text "Y" at 659.76,1334 h40 r270
  text "PIN2" at 1727.86,1282.97 h40
  text "PIN23" at 2093.12,1275.09 h40
  text "PIR1" at 1917.54,1273.71 h40
  text "X" at 611.25,1175.78 h40 r270
  text "Y" at 1206.52,1071.78 h40
  text "X" at 1361.24,915.25 h40
  text "Z" at 1206.52,910.03 h40
  text "Accelerometer / Gyroscope / 6 Axis Sensor" at 1877.93,908.49 h30 r90
  text "PIN6" at 68.47,773.84 h40 r90
  text "Ambient / Light  / Sensor" at 839.44,663.68 h35
  text "PIR2" at 66.17,567.59 h40 r90
  text "A- / MIC" at 822.75,543.57 h40
  text "I2S IN" at 843.07,395.48 h40
  text "Air  / Pressure / Sensor" at 414.46,355.6 h35
  text "PIN24" at 72.96,350 h40 r90
  text "D- / MIC" at 824.93,277.23 h40
  text "Digital  / MIC" at 938.53,153.53 h35
  text "Analog  / MIC" at 1644.4,109.15 h35
  text "TIDA-010997 Edge AI Sensors BoosterPack / Rev 2.0-B" at 395.37,16.16 h40
  text ".Layer_Name" at 577,-858.49 h60
Bottom Overlay:
  lines w4: 403.74,1184.87 403.74,1712.6 957.01,1712.6 957.01,1184.87 403.74,1184.87 ; 1223.45,1102.03 1812.73,1102.03 1812.73,1673.23 1223.45,1673.23 1223.45,1102.03
  text "Magnet Sensor" at 1751.37,1613.89 h40
  text "Temperature & Humidity Sensor" at 925.43,1200.2 h40
  text ".Layer_Name" at 577,-858.49 h60
Top Paste:
  text ".Layer_Name" at 577,-858.49 h60
Bottom Paste:
  text ".Layer_Name" at 577,-858.49 h60
Top Solder:
  text ".Layer_Name" at 577,-858.49 h60
  text ".Layer_Name" at 577,-858.49 h60
Bottom Solder:
  text ".Layer_Name" at 577,-858.49 h60
Drill Guide:
  text ".Layer_Name" at 577,-858.49 h60
M1 Board Outline:
  text ".Layer_Name" at 577,-858.49 h60
M2 Board Dimensions:
  rectangle: 0,-275 125,-150
  rectangle: 125,-400 500,-275
  lines w7: 0,-275 1000,-275 ; 125,-400 125,-150 ; 250,-400 250,-150 ; 500,-400 500,-150 ; 750,-400 750,-150 ; 0,-150 1000,-150 ; 0,-150 1000,-150 ; 0,-150 0,-400 1000,-400 1000,-150
  text ".Layer_Name" at 577,-858.49 h60
M3 3D STEP Top:
  text ".Layer_Name" at 577,-858.49 h60
M4 3D STEP Bottom:
  text ".Layer_Name" at 577,-858.49 h60
M5 Assembly Top:
  lines w10: -292,-930.17 6308,-930.17 ; -292,-726.83 6310,-726.83 ; -292,-523.5 -292,-1133.5 3713,-1133.5 6310,-1133.5 6310,-523.5 -291.5,-523.5 -291.5,-1133.5 1284,-1133.5 ; 2173,-1133.5 2173,-523.5 ; 3440,-726.83 3440,-523.5 ; 4280,-726.83 4280,-523.5 ; 4902,-1140 4902,-937.17
  text "COMPONENTS MARKED 'DNP' SHOULD NOT BE POPULATED." at 1153.5,-318.5 h60
  text "ASSEMBLY VARIANT:" at 1153,-434 h60
  text ".VariantName" at 2189,-434 h60
  text "PCB VIEWED FROM TOP SIDE" at -228.5,-655.67 h60
  text "BOARD #:" at 2248,-655.67 h60
  text ".PRJ_Number" at 2793.5,-655.67 h60
  text "REV:" at 3638,-655.67 h60
  text ".PCB_Rev" at 3929.5,-655.67 h60
  text "SVN REV:" at 4476,-655.67 h60
  text ".VersionControl_RevNumber" at 4982,-655.67 h60
  text "TID #:" at 2248,-859 h60
  text ".TID" at 2793.5,-859 h60
  text "PLOT NAME =" at -228.5,-1064.34 h60
  text ".plot_File_Name" at 577,-1064.34 h60
  text "GENERATED    :" at 2250,-1064.34 h60
  text ".Print_Date" at 3119.5,-1064.34 h60
  text ".Print_Time" at 3848.5,-1064.34 h60
  text "TEXAS INSTRUMENTS" at 5113,-1064.34 h60
M6 Assembly Bottom:
  lines w10: -292.5,-727.33 6309.5,-727.33 ; -290.5,-930.67 6309.5,-930.67 ; 1115.5,-1140.5 1115.5,-937.67 ; 1737.5,-727.33 1737.5,-524 ; 2577.5,-727.33 2577.5,-524 ; 3844.5,-1134 3844.5,-524 ; 4733.5,-1134 6309,-1134 6309,-524 -292.5,-524 -292.5,-1134 2304.5,-1134 6309.5,-1134 6309.5,-524
  text "COMPONENTS MARKED 'DNP' SHOULD NOT BE POPULATED." at 6102,-318 h60
  text ".VariantName" at 5058,-434 h60
  text "ASSEMBLY VARIANT:" at 6097,-434 h60
  text ".VersionControl_RevNumber" at 1035.5,-656.17 h60
  text "SVN REV:" at 1541.5,-656.17 h60
  text ".PCB_Rev" at 2088,-656.17 h60
  text "REV:" at 2379.5,-656.17 h60
  text ".PRJ_Number" at 3224,-656.17 h60
  text "BOARD #:" at 3769.5,-656.17 h60
  text "PCB VIEWED FROM BOTTOM SIDE" at 6246,-656.17 h60
  text ".TID" at 3224,-859.5 h60
  text "TID #:" at 3769.5,-859.5 h60
  text "TEXAS INSTRUMENTS" at 904.5,-1064.84 h60
  text ".Print_Time" at 2169,-1064.84 h60
  text ".Print_Date" at 2898,-1064.84 h60
  text "GENERATED    :" at 3767.5,-1064.84 h60
  text ".plot_File_Name" at 5440.5,-1064.84 h60
  text "PLOT NAME =" at 6246,-1064.84 h60
M7 LPKF Text Top:
M8 LPKF Text Bottom:
M9 Title Sheet:
  drawing of 57 lines, arcs and shapes, not listed
  text "1" at 739.84,8036.5 h70
  text "2" at 3235.5,8036.5 h70
  text "3" at 5724.84,8036.5 h70
  text "4" at 8231.51,8036.5 h70
  text "5" at 10730.5,8036.5 h70
  text "6" at 13235.5,8036.5 h70
  text "A" at -416.5,6893.5 h70
  text "A" at 14383.5,6893.5 h70
  text "B" at -416.5,4513.5 h70
  text "B" at 14383.5,4513.5 h70
  text "C" at -416.5,2138.5 h70
  text "C" at 14383.5,2138.5 h70
  text "PROJECT TITLE:" at 11343.5,277.5 h45
  text ".PRJ_Title" at 11393.5,144.17 h70
  text "DESIGNED FOR:" at 11343.5,-23.5 h45
  text ".PRJ_Customer" at 11393.5,-163.5 h70
  text "D" at -416.5,-231.5 h70
  text "D" at 14383.5,-231.5 h70
  text "FILE NAME:" at 11343.5,-323.5 h45
  text ".PCB_File_Name_No_Path" at 11393.5,-443.5 h70
  text "Texas Instruments (TI) and/or its licensors do not warrant the accuracy or completeness of this specification" at 6374,-605.34 h45
  text "ENGINEER:" at 11343.5,-613.5 h45
  text "LAYOUT BY:" at 12848.5,-613.5 h45
  text "or any information contained therein. TI and/or its licensors do not warrant that this design will meet" at 6329.01,-718 h45
  text ".PRJ_Engineer" at 11393.5,-768.49 h70
  text ".PCB_Layout" at 12899,-768.49 h70
  text "the specifications, will be suitable for your application or fit for any particular purpose, or will operate in" at 6329.01,-830.67 h45
  text ".Layer_Name" at 577,-858.49 h60
  text "ALTIUM DESIGNER VERSION:" at 12848.5,-923.5 h45
  text "an implementation. TI and/or its licensors do not warrant that the design is production worthy. You should" at 6329.01,-943.33 h45
  text "completely validate and test your design implementation to confirm the system functionality for your application." at 6374,-1056 h45
  text ".print_Scale" at 11393.5,-1056.83 h70
  text ".Application_BuildNumber" at 12899,-1056.83 h70
  text "1" at 739.84,-1263.5 h70
  text "2" at 3235.5,-1263.5 h70
  text "3" at 5724.84,-1263.5 h70
  text "4" at 8231.51,-1263.5 h70
  text "5" at 10730.5,-1263.5 h70
  text "6" at 13235.5,-1263.5 h70
M10 Fab Notes:
  drawing of 189 lines, arcs and shapes, not listed
  text "DESIGN INFORMATION" at 12382.02,6356.17 h60
  text "MIN. TRACK WIDTH:" at 11737.46,6224.05 h60
  text "6" at 12833.7,6224.05 h60
  text "MIL" at 12988.46,6224.05 h60
  text "7.874" at 12667.32,6102.36 h60
  text "MIN. CLEARANCE:" at 11737.46,6099.92 h60
  text "MIL" at 12988.46,6099.92 h60
  text "MIN. VIA PAD SIZE:" at 11737.46,5975.8 h60
  text "24" at 12803.71,5975.8 h60
  text "MIL" at 12988.46,5975.8 h60
  text "0.05mm (2MIL)" at 12432.46,5845.9 h60
  text "MINIMUM ANNULAR RING" at 11408.23,5837.67 h60
  text "EXTERNAL" at 13140.46,5837.67 h60
  text "PER" at 11608.23,5727.55 h60
  text "IPC-D-275 CLASS 2 LEVEL C" at 11828.23,5727.54 h60
  text "MIL, HOLES" at 13316.46,5627.07 h60
  text "+/-" at 12924,5618.48 h60
  text "+/-" at 13778,5618.48 h60
  text "REGISTRATION TOLERANCES:" at 11408.23,5617.42 h60
  text "METAL" at 12608,5617.42 h60
  text "5" at 13184.2,5617.42 h60
  text "3" at 14017.2,5617.42 h60
  text "MIL" at 14133.46,5617.42 h60
  text "HOLE SIZE TOLERANCE (UNLESS OTHERWISE SPECIFIED):" at 11408.23,5519.1 h60
  text "+/-" at 13778,5516.23 h60
  text "3" at 14017.2,5515.17 h60
  text "MIL" at 14133.46,5515.17 h60
  text "MATERIAL:" at 11333.46,5377.52 h60
  text "FR-4 High Tg" at 12319.9,5249 h60
  text "X" at 12175.46,5241.01 h60
  text "FR-408" at 11754.46,5236.49 h60
  text "OTHER" at 13242.46,5236.49 h60
  text "62 MIL (1.6mm) +/-10%" at 12074.56,5093.46 h60
  text "X" at 11954.46,5091.01 h60
  text "THICKNESS:" at 11408.23,5085.24 h60
  text "OTHER" at 13359.46,5085.24 h60
  text "TOLERANCE:" at 11408.23,4946.92 h60
  text "X" at 12256.46,4946.92 h60
  text "ANSI IPC-6012 TYPE 3 CLASS 2" at 12434.48,4946.92 h60
  text "OTHER +/-" at 12434.46,4802.73 h60
  text "BOW & TWIST:" at 11408.23,4657.54 h60
  text "X" at 12256.46,4657.54 h60
  text "ANSI IPC-6012 TYPE 3 CLASS 2" at 12434.48,4657.54 h60
  text "OTHER +/-" at 12434.46,4510.85 h60
  text "DRILLING:" at 11333.46,4380.23 h60
  text "NC_DRILL FILES" at 13094.46,4275.04 h60
  text "REFERENCE:" at 11408.23,4271.1 h60
  text "X" at 12065.46,4271.01 h60
  text "AS SHOWN" at 12243.46,4271.1 h60
  text "X" at 12966.46,4271.1 h60
  text "OTHER" at 13392.46,4128.85 h60
  text "PTH COPPER THICKNESS:" at 11407.91,4125.32 h60
  text "X" at 12547.14,4125.32 h60
  text "20-30 um" at 12675.14,4125.32 h60
  text "BOARD FINISH:" at 11333.46,3977.73 h60
  text "SILKSCREEN:" at 11488.68,3867.6 h60
  text "X" at 12446.46,3867.6 h60
  text "TOP" at 12563.46,3867.6 h60
  text "X" at 12956.46,3867.6 h60
  text "BOTTOM" at 13074.46,3867.6 h60
  text "SILKSCREEN COLOR:" at 11488.68,3712.41 h60
  text "X" at 12445.46,3712.41 h60
  text "WHITE" at 12563.46,3712.41 h60
  text "OTHER" at 13074.46,3712.41 h60
  text "GREEN" at 12694.46,3568.96 h60
  text "X" at 13169.29,3568.96 h60
  text "OTHER" at 13312.46,3568.96 h60
  text "RED" at 13690.94,3568.96 h60
  text "SOLDER RESIST COLOR:" at 11488.68,3562.1 h60
  text "MATTE" at 12694.46,3414.71 h60
  text "SEMI-GLOSS" at 13312,3414.07 h60
  text "IMMERSION GOLD (ENIG)" at 12394.46,3241.94 h60
  text "ENEPIG" at 13732,3234.72 h60
  text "SURFACE FINISH:" at 11333.46,3233.72 h60
  text "X" at 12216.46,3233.72 h60
  text "IMM. TIN/SILVER OR EQUIV" at 11663,3096.4 h60
  text "OTHER" at 13094.46,3092.47 h60
  text "ARRAY/PANEL:" at 11333.46,2937.09 h60
  text "CUT AND TRIM PER M1 BOARD OUTLINE" at 12394.46,2928.87 h60
  text "N.C. ROUTE" at 12394.46,2792.9 h60
  text "X" at 13082.46,2792.9 h60
  text "V. SCORE" at 13260.46,2792.9 h60
  text "CERTIFICATION:" at 11333.46,2663.77 h60
  text "MATERIALS AND WORKMANSHIP FOR ALL PCBS" at 12058.46,2663.77 h60
  text "TO MEET OR EXCEED THE REQUIREMENTS OF:" at 12058.46,2569.71 h60
  text "X" at 11695.97,2441.08 h60
  text "ANSI IPC-A-600F CLASS ->" at 11823.96,2441.08 h60
  text "X" at 13471.97,2441.08 h60
  text "2" at 13581.96,2441.08 h60
  text "1" at 13266.96,2439.58 h60
  text "3" at 13935.96,2439.58 h60
  text "X" at 12507.97,2293.39 h60
  text "RoHS" at 12635.96,2293.39 h60
  text "OTHER" at 13280.36,2293.39 h60
  text "PER ORDER" at 13677.42,2293.39 h60
  text "ALL BOARDS MUST MEET OR EXCEED UL94-V0 REQUIREMENTS." at 11361,2139.57 h60
  text "PCB MUST BEAR THE UL94V-0 UL REGISTERED MATERIAL ID NUMBER" at 11361,2023.5 h60
  text "ADDITIONAL REQUIREMENTS:" at 11333.46,1854.08 h60
  text "MICROSECTION:" at 11408.23,1746.95 h60
  text "YES" at 12313.96,1746.95 h60
  text "REQUIRED" at 13175.46,1602.62 h60
  text "X" at 13651.57,1602.62 h60
  text "BARE BOARD ELEC. TEST:" at 11408.23,1599.76 h60
  text "NONE" at 12713.96,1599.76 h60
  text "PER ORDER" at 13767.46,1599.76 h60
  text "XX MIL VIAS REQUIRE NON-CONDUCTIVE FILL AND PLANARIZE" at 11576.38,1394.82 h59
  text "XX MIL VIAS REQUIRE CONDUCTIVE FILL AND PLANARIZE" at 11584.38,1290.84 h60
  text "OUTER XX MIL TRACES REQUIRE 50 OHM SINGLE-ENDED IMPEDANCE" at 11583.39,1127.46 h58
  text "LAYER 2 & 3 (INNER LAYERS) XX MIL WIDE, XX MIL SPACE / TRACES REQUIRE 100 OHM DIFFERENTIAL IMPEDANCE" at 11575.39,891.74 h60
  text ".Layer_Name" at 577,-858.49 h60
M11 Gerber Information:
  lines w10: -292,-930.17 6308,-930.17 ; -292,-726.83 6310,-726.83 ; -292,-523.5 -292,-1133.5 3713,-1133.5 6310,-1133.5 6310,-523.5 -291.5,-523.5 -291.5,-1133.5 1284,-1133.5 ; 2173,-1133.5 2173,-523.5 ; 3440,-726.83 3440,-523.5 ; 4280,-726.83 4280,-523.5 ; 4902,-1140 4902,-937.17
  text "ALL ARTWORK VIEWED FROM TOP SIDE" at -228.5,-655.67 h60
  text "BOARD #:" at 2248,-655.67 h60
  text ".PRJ_Number" at 2793.5,-655.67 h60
  text "REV:" at 3638,-655.67 h60
  text ".PCB_Rev" at 3929.5,-655.67 h60
  text "SVN REV:" at 4476,-655.67 h60
  text ".VersionControl_RevNumber" at 4982,-655.67 h60
  text "LAYER NAME =" at -228.5,-858.49 h60
  text "TID #:" at 2248,-859 h60
  text ".TID" at 2793.5,-859 h60
  text "PLOT NAME =" at -228.5,-1064.34 h60
  text ".plot_File_Name" at 577,-1064.34 h60
  text "GENERATED    :" at 2250,-1064.34 h60
  text ".Print_Date" at 3119.5,-1064.34 h60
  text ".Print_Time" at 3848.5,-1064.34 h60
  text "TEXAS INSTRUMENTS" at 5113,-1064.34 h60
M12 Stackup:
  drawing of 191 lines, arcs and shapes, not listed
  text "Layer" at 9634.82,7688.04 h60
  text "Name" at 10044.73,7688.04 h60
  text "Material" at 10974.48,7688.04 h60
  text "Thickness" at 11834.24,7688.04 h60
  text "Constant" at 12484.08,7688.04 h60
  text "Board Layer Stack" at 13053.94,7688.04 h60
  text "Top Overlay" at 10044.73,7568.04 h60
  text "Top Solder" at 10044.73,7448.04 h60
  text "Solder Resist" at 10974.48,7448.04 h60
  text "0.40mil" at 11834.24,7448.04 h60
  text "3.5" at 12484.08,7448.04 h60
  text "1" at 9634.82,7328.04 h60
  text "Top Layer" at 10044.73,7328.04 h60
  text "1.40mil" at 11834.24,7328.04 h60
  text "Dielectric1" at 10044.73,7208.04 h60
  text "FR-4 High Tg" at 10974.48,7208.04 h60
  text "59.20mil" at 11834.24,7208.04 h60
  text "4.8" at 12484.08,7208.04 h60
  text "2" at 9634.82,7088.04 h60
  text "Bottom Layer" at 10044.73,7088.04 h60
  text "1.40mil" at 11834.24,7088.04 h60
  text "Bottom Solder" at 10044.73,6968.04 h60
  text "Solder Resist" at 10974.48,6968.04 h60
  text "0.40mil" at 11834.24,6968.04 h60
  text "3.5" at 12484.08,6968.04 h60
  text "Bottom Overlay" at 10044.73,6848.04 h60
  text ".Layer_Name" at 577,-858.49 h60
M13 Component Bodies Top:
  text ".Layer_Name" at 577,-858.49 h60
M14 Component Bodies Bottom:
  text ".Layer_Name" at 577,-858.49 h60
M15 Courtyards Top:
  text ".Layer_Name" at 577,-858.49 h60
M16 Courtyards Bottom:
  text ".Layer_Name" at 577,-858.49 h60
Drill Drawing:
  circle w10: c5363.63,3290.5 r16.56
  circle w10: c5363.63,3290.5 r27.59
  circle w10: c5363.63,2545.44 r27.59
  lines w10: 5336.04,2448.86 5391.23,2448.86 5363.63,2393.67 5336.04,2448.86 ; 5336.04,2655.82 5349.83,2655.82 5363.63,2642.02 5377.43,2655.82 5391.23,2655.82 5377.43,2669.62 5391.23,2683.41 5377.43,2683.41 5363.63,2697.21 5349.83,2683.41 5336.04,2683.41 5349.83,2669.62 5336.04,2655.82 ; 5336.04,2779.99 5349.83,2779.99 5363.63,2766.2 5377.43,2779.99 5391.23,2779.99 5377.43,2793.79 5391.23,2807.59 5377.43,2807.59 5363.63,2821.39 5349.83,2807.59 5336.04,2807.59 5349.83,2793.79 5336.04,2779.99 ; 5336.04,2890.37 5391.23,2890.37 5391.23,2945.56 5336.04,2945.56 5336.04,2890.37 ; 5336.04,3014.55 5363.63,3028.35 5391.23,3014.55 5377.43,3042.14 5391.23,3069.74 5363.63,3055.94 5336.04,3069.74 5349.83,3042.14 5336.04,3014.55 ; 5336.04,3138.72 5391.23,3138.72 5391.23,3193.91 5336.04,3193.91 5336.04,3138.72 ; 5347.07,2437.82 5380.19,2437.82 5363.63,2404.71 5347.07,2437.82 ; 5347.07,2661.34 5355.35,2661.34 5363.63,2653.06 5371.91,2661.34 5380.19,2661.34 5371.91,2669.62 5380.19,2677.89 5371.91,2677.89 5363.63,2686.17 5355.35,2677.89 5347.07,2677.89 5355.35,2669.62 5347.07,2661.34 ; 5347.07,3025.59 5363.63,3033.87 5380.19,3025.59 5371.91,3042.14 5380.19,3058.7 5363.63,3050.42 5347.07,3058.7 5355.35,3042.14 5347.07,3025.59 ; 5347.07,3149.76 5380.19,3149.76 5380.19,3182.88 5347.07,3182.88 5347.07,3149.76
  lines w12: 5286,2356.42 8516.52,2356.42 ; 5286,3349.82 8516.52,3349.82 ; 5623.86,2232.24 5623.86,3474 ; 5955.86,2232.24 5955.86,3474 ; 6592.42,2232.24 6592.42,3474 ; 6851.53,2232.24 6851.53,3474 ; 7226.68,2232.24 7226.68,3474 ; 7950.06,2232.24 7950.06,3474 ; 5286,2232.24 8516.52,2232.24 8516.52,3474 5286,3474 5286,2232.24
  text "Symbol" at 5360.51,3387.08 h72
  text "Quantity" at 5661.11,3387.08 h72
  text "Finished Hole Size" at 5993.12,3387.08 h72
  text "Plated" at 6629.67,3387.08 h72
  text "Hole Type" at 6888.78,3387.08 h72
  text "Drill Layer Pair" at 7263.93,3387.08 h72
  text "Hole Tolerance" at 7987.32,3387.08 h72
  text "1" at 5661.11,3262.9 h60
  text "19.69mil (0.500mm)" at 5993.12,3262.9 h60
  text "NPTH" at 6629.67,3262.9 h60
  text "Round" at 6888.78,3262.9 h60
  text "Top Layer - Bottom Layer" at 7263.93,3262.9 h60
  text "1" at 5661.11,3138.72 h60
  text "39.37mil (1.000mm)" at 5993.12,3138.72 h60
  text "NPTH" at 6629.67,3138.72 h60
  text "Round" at 6888.78,3138.72 h60
  text "Top Layer - Bottom Layer" at 7263.93,3138.72 h60
  text "6" at 5661.11,3014.55 h60
  text "7.87mil (0.200mm)" at 5993.12,3014.55 h60
  text "PTH" at 6629.67,3014.55 h60
  text "Round" at 6888.78,3014.55 h60
  text "Top Layer - Bottom Layer" at 7263.93,3014.55 h60
  text "271" at 5661.11,2890.37 h60
  text "8.00mil (0.203mm)" at 5993.12,2890.37 h60
  text "PTH" at 6629.67,2890.37 h60
  text "Round" at 6888.78,2890.37 h60
  text "Top Layer - Bottom Layer" at 7263.93,2890.37 h60
  text "6" at 5661.11,2766.2 h60
  text "29.53mil (0.750mm)" at 5993.12,2766.2 h60
  text "PTH" at 6629.67,2766.2 h60
  text "Round" at 6888.78,2766.2 h60
  text "Top Layer - Bottom Layer" at 7263.93,2766.2 h60
  text "15" at 5661.11,2642.02 h60
  text "33.47mil (0.850mm)" at 5993.12,2642.02 h60
  text "PTH" at 6629.67,2642.02 h60
  text "Round" at 6888.78,2642.02 h60
  text "Top Layer - Bottom Layer" at 7263.93,2642.02 h60
  text "40" at 5661.11,2517.84 h60
  text "40.16mil (1.020mm)" at 5993.12,2517.84 h60
  text "PTH" at 6629.67,2517.84 h60
  text "Round" at 6888.78,2517.84 h60
  text "Top Layer - Bottom Layer" at 7263.93,2517.84 h60
  text "2" at 5661.11,2393.67 h60
  text "62.99mil (1.600mm)" at 5993.12,2393.67 h60
  text "PTH" at 6629.67,2393.67 h60
  text "Round" at 6888.78,2393.67 h60
  text "Top Layer - Bottom Layer" at 7263.93,2393.67 h60
  text "342 Total" at 5661.11,2269.49 h60
  text ".Layer_Name" at 577,-858.49 h60
M17 Embedded Cavity:
  text ".Layer_Name" at 577,-858.49 h60
M18 Embedded Assembly:
  text ".Layer_Name" at 577,-858.49 h60
M19 Embedded Keepout:
  text ".Layer_Name" at 577,-858.49 h60
Dimensions:
  the board outline again, w10

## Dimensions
5,1805 to 5,5 on M1 Board Outline
5,5 to 2305,5 on M2 Board Dimensions
0,-400 to 1000,-400 on M2 Board Dimensions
